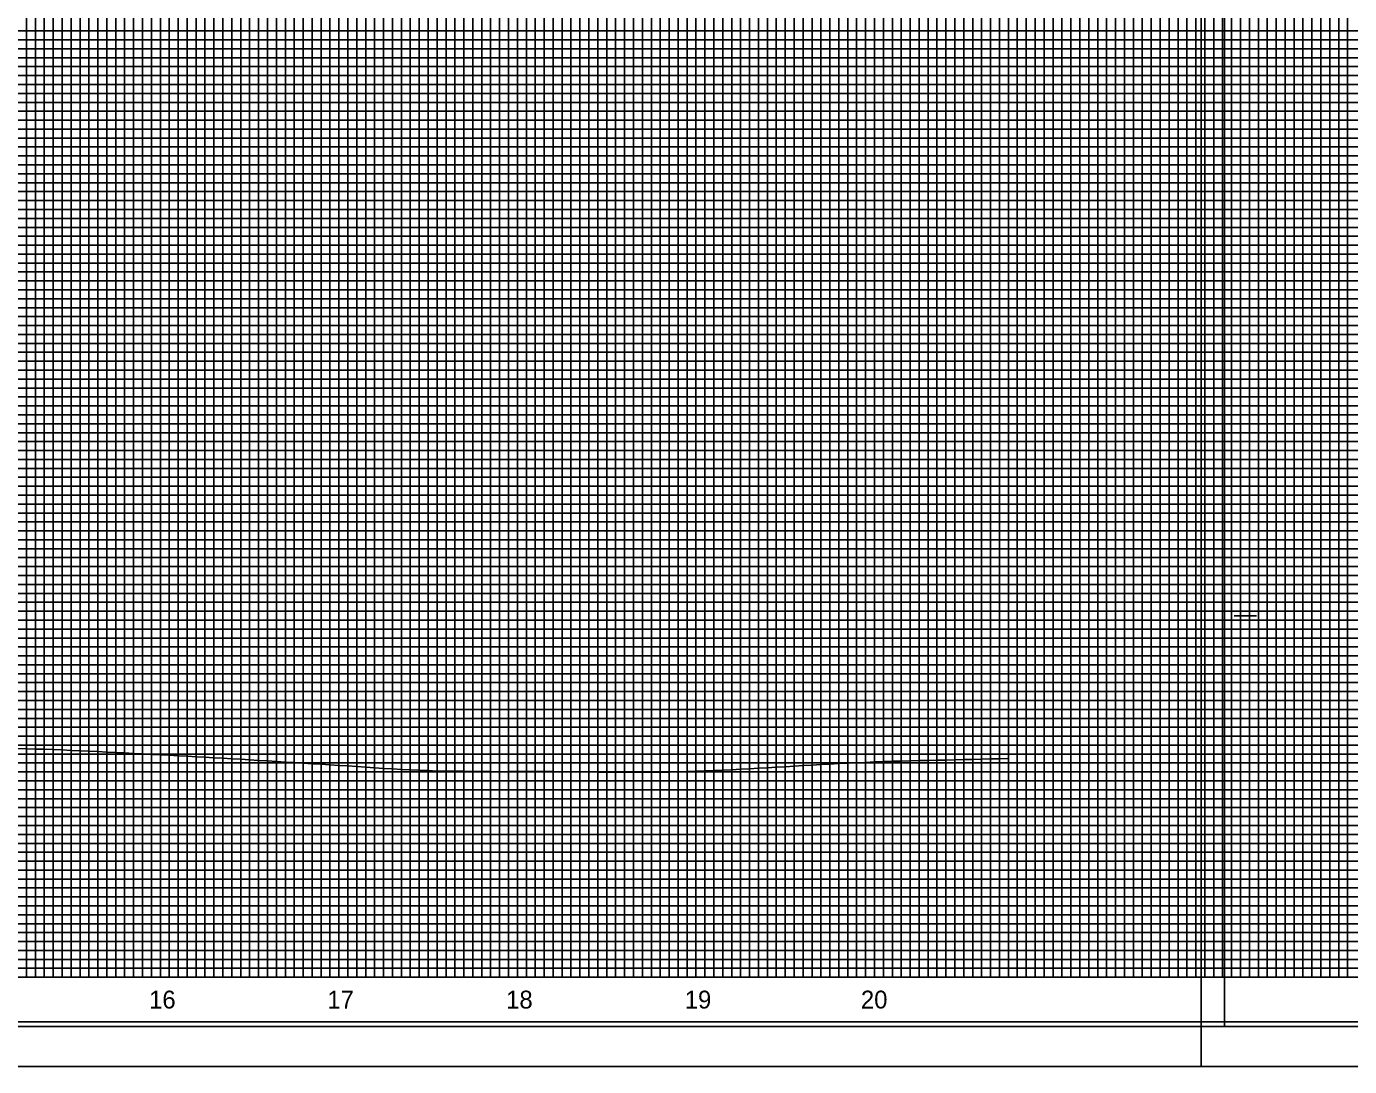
# Model space of a CAD drawing. Extents: x 2345490 to 2445302, y 465165 to 573888.
# Drawn here: x 2382292 to 2383033, y 532361 to 532944 of the extents above; entities that cross this region are included whole.
import ezdxf

# ---------------------------------------------------------------- set-up
doc = ezdxf.new("R2010")
doc.units = 0
for name, color, linetype in [('Old_Level_1', 7, 'Continuous'), ('Old_Level_18', 7, 'Continuous'), ('Old_Level_41', 7, 'Continuous'), ('Old_Level_42', 7, 'Continuous'), ('Old_Level_43', 7, 'Continuous'), ('Old_Level_50', 7, 'Continuous'), ('Old_Level_51', 7, 'Continuous'), ('Old_Level_52', 7, 'Continuous'), ('Old_Level_62', 7, 'Continuous')]:
    doc.layers.add(name, color=color, linetype=linetype)

msp = doc.modelspace()

# ---------------------------------------------------------------- linework, layer by layer
at = {"layer": 'Old_Level_1'}
for points in [[(2382286.799, 532539.1095), (2382291.799, 532538.9875), (2382296.799, 532538.85975), (2382301.799, 532538.726), (2382306.799, 532538.5865), (2382311.799, 532538.377), (2382316.799, 532538.132), (2382321.799, 532537.8975), (2382326.799, 532537.65625), (2382331.799, 532537.4085), (2382336.799, 532537.15425), (2382341.799, 532536.908), (2382346.799, 532536.6585), (2382351.799, 532536.403), (2382356.799, 532536.14075), (2382361.799, 532535.87225), (2382366.799, 532535.60075), (2382371.799, 532535.38675), (2382376.799, 532535.12375), (2382381.799, 532534.849), (2382386.799, 532534.5685), (2382391.799, 532534.282), (2382396.799, 532533.99625), (2382401.799, 532533.748), (2382406.799, 532533.447), (2382411.799, 532533.1405), (2382416.799, 532532.8285), (2382421.799, 532532.51075), (2382426.799, 532532.18825), (2382431.799, 532531.8715), (2382436.799, 532531.56825), (2382441.799, 532531.25975), (2382446.799, 532530.94575), (2382451.799, 532530.6265), (2382456.799, 532530.3015), (2382461.799, 532529.98825), (2382466.799, 532529.706), (2382471.799, 532529.38325), (2382476.799, 532529.05375), (2382481.799, 532528.71925), (2382486.799, 532528.37975), (2382491.799, 532528.03575), (2382496.799, 532527.726), (2382501.799, 532527.4785), (2382506.799, 532527.238), (2382511.799, 532526.99725), (2382516.799, 532526.7565), (2382521.799, 532526.516), (2382526.799, 532526.498), (2382531.799, 532526.46275), (2382536.799, 532526.39975), (2382541.799, 532526.3365), (2382546.799, 532526.2735), (2382551.799, 532526.21025), (2382556.799, 532526.18925), (2382561.799, 532526.358), (2382566.799, 532526.34), (2382571.799, 532526.32175), (2382576.799, 532526.30375), (2382581.799, 532526.2855), (2382586.799, 532526.26725), (2382591.799, 532526.192), (2382596.799, 532526.11125), (2382601.799, 532526.06925), (2382606.799, 532526.02725), (2382611.799, 532525.985), (2382616.799, 532525.943), (2382621.799, 532525.88875), (2382626.799, 532525.86325), (2382631.799, 532525.86525), (2382636.799, 532525.86725), (2382641.799, 532525.869), (2382646.799, 532525.871), (2382651.799, 532525.968), (2382656.799, 532526.135), (2382661.799, 532526.315), (2382666.799, 532526.49525), (2382671.799, 532526.67525), (2382676.799, 532526.8555), (2382681.799, 532527.05), (2382686.799, 532527.29475), (2382691.799, 532527.573), (2382696.799, 532527.851), (2382701.799, 532528.12925), (2382706.799, 532528.4075), (2382711.799, 532528.67275), (2382716.799, 532528.94875), (2382721.799, 532529.25225), (2382726.799, 532529.556), (2382731.799, 532529.8595), (2382736.799, 532530.163), (2382741.799, 532530.4535), (2382746.799, 532530.685), (2382751.799, 532530.9185), (2382756.799, 532531.152), (2382761.799, 532531.3855), (2382766.799, 532531.61925)], [(2382766.799, 532531.61925), (2382771.799, 532531.85275), (2382776.799, 532532.025), (2382781.799, 532532.15675), (2382786.799, 532532.2705), (2382791.799, 532532.38425), (2382796.799, 532532.49775), (2382801.799, 532532.6115), (2382806.799, 532532.726), (2382811.799, 532532.84175), (2382816.799, 532532.95525), (2382821.799, 532533.06875), (2382826.799, 532533.182), (2382831.799, 532533.2955), (2382836.799, 532533.409), (2382841.349, 532533.50025)]]:
    msp.add_lwpolyline(points, dxfattribs=at)
at = {"layer": 'Old_Level_18'}
msp.add_lwpolyline([(2383216.79875, 533436.04975), (2381716.79875, 533436.04975), (2381716.79875, 532386.04975), (2383216.79875, 532386.04975)], close=True, dxfattribs=at)
at = {"layer": 'Old_Level_41'}
for p, q in [((2382968.29875, 532613.54975), (2382980.79875, 532613.54975)), ((2383216.79875, 532411.04975), (2381716.79875, 532411.04975))]:
    msp.add_line(p, q, dxfattribs=at)
for points in [[(2382241.79875, 532411.04975), (2382291.79875, 532411.04975), (2382291.79875, 533436.04975)], [(2382266.79875, 532411.04975), (2382316.79875, 532411.04975), (2382316.79875, 533436.04975)], [(2382341.79875, 533436.04975), (2382341.79875, 532411.04975), (2382391.79875, 532411.04975), (2382391.79875, 533436.04975)], [(2382366.79875, 533436.04975), (2382366.79875, 532411.04975), (2382416.79875, 532411.04975), (2382416.79875, 533436.04975)], [(2382441.79875, 533436.04975), (2382441.79875, 532411.04975), (2382491.79875, 532411.04975), (2382491.79875, 533436.04975)], [(2382466.79875, 533436.04975), (2382466.79875, 532411.04975), (2382516.79875, 532411.04975), (2382516.79875, 533436.04975)], [(2382541.79875, 533436.04975), (2382541.79875, 532411.04975), (2382591.79875, 532411.04975), (2382591.79875, 533436.04975)], [(2382566.79875, 533436.04975), (2382566.79875, 532411.04975), (2382616.79875, 532411.04975), (2382616.79875, 533436.04975)], [(2382641.79875, 533436.04975), (2382641.79875, 532411.04975), (2382691.79875, 532411.04975), (2382691.79875, 533436.04975)], [(2382666.79875, 533436.04975), (2382666.79875, 532411.04975), (2382716.79875, 532411.04975), (2382716.79875, 533436.04975)], [(2382741.79875, 533436.04975), (2382741.79875, 532411.04975), (2382791.79875, 532411.04975), (2382791.79875, 533436.04975)], [(2382766.79875, 533436.04975), (2382766.79875, 532411.04975), (2382816.79875, 532411.04975), (2382816.79875, 533436.04975)], [(2382841.79875, 533436.04975), (2382841.79875, 532411.04975), (2382891.79875, 532411.04975), (2382891.79875, 533436.04975)], [(2382866.79875, 533436.04975), (2382866.79875, 532411.04975), (2382916.79875, 532411.04975), (2382916.79875, 533436.04975)], [(2382941.79875, 533436.04975), (2382941.79875, 532411.04975), (2382991.79875, 532411.04975), (2382991.79875, 533436.04975)], [(2382966.79875, 533436.04975), (2382966.79875, 532411.04975), (2383016.79875, 532411.04975), (2383016.79875, 533436.04975)], [(2383216.79875, 532936.04975), (2381716.79875, 532936.04975), (2381716.79875, 532886.04975), (2383216.79875, 532886.04975)], [(2383216.79875, 532836.04975), (2381716.79875, 532836.04975), (2381716.79875, 532786.04975), (2383216.79875, 532786.04975)], [(2383216.79875, 532761.04975), (2381716.79875, 532761.04975), (2381716.79875, 532811.04975), (2383216.79875, 532811.04975)], [(2383216.79875, 532736.04975), (2381716.79875, 532736.04975), (2381716.79875, 532686.04975), (2383216.79875, 532686.04975)], [(2383216.79875, 532661.04975), (2381716.79875, 532661.04975), (2381716.79875, 532711.04975), (2383216.79875, 532711.04975)], [(2383216.79875, 532636.04975), (2381716.79875, 532636.04975), (2381716.79875, 532586.04975), (2383216.79875, 532586.04975)], [(2383216.79875, 532536.04975), (2381716.79875, 532536.04975), (2381716.79875, 532486.04975), (2383216.79875, 532486.04975)], [(2383216.79875, 532461.04975), (2381716.79875, 532461.04975), (2381716.79875, 532511.04975), (2383216.79875, 532511.04975)], [(2383216.79875, 532436.04975), (2381716.79875, 532436.04975)]]:
    msp.add_lwpolyline(points, dxfattribs=at)
at = {"layer": 'Old_Level_42'}
for points in [[(2383216.79875, 532861.04975), (2381716.79875, 532861.04975), (2381716.79875, 532911.04975), (2383216.79875, 532911.04975)], [(2383216.79875, 532561.04975), (2381716.79875, 532561.04975), (2381716.79875, 532611.04975), (2383216.79875, 532611.04975)]]:
    msp.add_lwpolyline(points, dxfattribs=at)
at = {"layer": 'Old_Level_43'}
for points in [[(2382296.79875, 532411.04975), (2382296.79875, 533436.04975)], [(2382301.79875, 533436.04975), (2382301.79875, 532411.04975), (2382306.79875, 532411.04975), (2382306.79875, 533436.04975)], [(2382311.79875, 533436.04975), (2382311.79875, 532411.04975), (2382321.79875, 532411.04975), (2382321.79875, 533436.04975)], [(2382326.79875, 533436.04975), (2382326.79875, 532411.04975), (2382326.79875, 532411.04975), (2382331.79875, 532411.04975), (2382331.79875, 533436.04975)], [(2382336.79875, 533436.04975), (2382336.79875, 532411.04975), (2382346.79875, 532411.04975), (2382346.79875, 533436.04975)], [(2382351.79875, 533436.04975), (2382351.79875, 532411.04975), (2382356.79875, 532411.04975), (2382356.79875, 533436.04975)], [(2382361.79875, 533436.04975), (2382361.79875, 532411.04975), (2382371.79875, 532411.04975), (2382371.79875, 533436.04975)], [(2382376.79875, 533436.04975), (2382376.79875, 532411.04975), (2382381.79875, 532411.04975), (2382381.79875, 533436.04975)], [(2382386.79875, 533436.04975), (2382386.79875, 532411.04975), (2382396.79875, 532411.04975), (2382396.79875, 533436.04975)], [(2382401.79875, 533436.04975), (2382401.79875, 532411.04975), (2382406.79875, 532411.04975), (2382406.79875, 533436.04975)], [(2382411.79875, 533436.04975), (2382411.79875, 532411.04975), (2382421.79875, 532411.04975), (2382421.79875, 533436.04975)], [(2382426.79875, 533436.04975), (2382426.79875, 532411.04975), (2382431.79875, 532411.04975), (2382431.79875, 533436.04975)], [(2382436.79875, 533436.04975), (2382436.79875, 532411.04975), (2382446.79875, 532411.04975), (2382446.79875, 533436.04975)], [(2382451.79875, 533436.04975), (2382451.79875, 532411.04975), (2382456.79875, 532411.04975), (2382456.79875, 533436.04975)], [(2382461.79875, 533436.04975), (2382461.79875, 532411.04975), (2382471.79875, 532411.04975), (2382471.79875, 533436.04975)], [(2382476.79875, 533436.04975), (2382476.79875, 532411.04975)], [(2382476.79875, 532411.04975), (2382481.79875, 532411.04975), (2382481.79875, 533435.44975)], [(2382486.79875, 533435.44975), (2382486.79875, 532411.04975), (2382496.79875, 532411.04975), (2382496.79875, 533436.04975)], [(2382501.79875, 533436.04975), (2382501.79875, 532411.04975), (2382506.79875, 532411.04975), (2382506.79875, 533436.04975)], [(2382511.79875, 533436.04975), (2382511.79875, 532411.04975), (2382521.79875, 532411.04975), (2382521.79875, 533436.04975)], [(2382526.79875, 533436.04975), (2382526.79875, 532411.04975), (2382531.79875, 532411.04975), (2382531.79875, 533436.04975)], [(2382536.79875, 533436.04975), (2382536.79875, 532411.04975), (2382546.79875, 532411.04975), (2382546.79875, 533436.04975)], [(2382551.79875, 533436.04975), (2382551.79875, 532411.04975), (2382556.79875, 532411.04975), (2382556.79875, 533436.04975)], [(2382561.79875, 533436.04975), (2382561.79875, 532411.04975), (2382571.79875, 532411.04975), (2382571.79875, 533436.04975)], [(2382576.79875, 533436.04975), (2382576.79875, 532411.04975), (2382581.79875, 532411.04975), (2382581.79875, 533436.04975)], [(2382586.79875, 533436.04975), (2382586.79875, 532411.04975), (2382596.79875, 532411.04975), (2382596.79875, 533436.04975)], [(2382601.79875, 533436.04975), (2382601.79875, 532411.04975), (2382606.79875, 532411.04975), (2382606.79875, 533436.04975)], [(2382611.79875, 533436.04975), (2382611.79875, 532411.04975), (2382621.79875, 532411.04975), (2382621.79875, 533436.04975)], [(2382626.79875, 533436.04975), (2382626.79875, 532411.04975), (2382631.79875, 532411.04975), (2382631.79875, 533436.04975)], [(2382636.79875, 533436.04975), (2382636.79875, 532411.04975), (2382646.79875, 532411.04975), (2382646.79875, 533436.04975)], [(2382651.79875, 533436.04975), (2382651.79875, 532411.04975), (2382656.79875, 532411.04975), (2382656.79875, 533436.04975)], [(2382661.79875, 533436.04975), (2382661.79875, 532411.04975), (2382671.79875, 532411.04975), (2382671.79875, 533436.04975)], [(2382676.79875, 533436.04975), (2382676.79875, 532411.04975), (2382681.79875, 532411.04975), (2382681.79875, 533436.04975)], [(2382686.79875, 533436.04975), (2382686.79875, 532411.04975), (2382696.79875, 532411.04975), (2382696.79875, 533436.04975)], [(2382701.79875, 533436.04975), (2382701.79875, 532411.04975), (2382706.79875, 532411.04975), (2382706.79875, 533436.04975)], [(2382711.79875, 533436.04975), (2382711.79875, 532411.04975), (2382721.79875, 532411.04975), (2382721.79875, 533436.04975)], [(2382726.79875, 533436.04975), (2382726.79875, 532411.04975), (2382731.79875, 532411.04975), (2382731.79875, 533436.04975)], [(2382736.79875, 533436.04975), (2382736.79875, 532411.04975), (2382746.79875, 532411.04975), (2382746.79875, 533436.04975)], [(2382751.79875, 533436.04975), (2382751.79875, 532411.04975), (2382756.79875, 532411.04975), (2382756.79875, 533436.04975)], [(2382761.79875, 533436.04975), (2382761.79875, 532411.04975), (2382771.79875, 532411.04975), (2382771.79875, 533436.04975)], [(2382776.79875, 533436.04975), (2382776.79875, 532411.04975), (2382781.79875, 532411.04975), (2382781.79875, 533436.04975)], [(2382786.79875, 533436.04975), (2382786.79875, 532411.04975)], [(2382786.79875, 532411.04975), (2382796.79875, 532411.04975), (2382796.79875, 533436.04975)], [(2382801.79875, 533436.04975), (2382801.79875, 532411.04975), (2382806.79875, 532411.04975), (2382806.79875, 533436.04975)], [(2382811.79875, 533436.04975), (2382811.79875, 532411.04975), (2382821.79875, 532411.04975), (2382821.79875, 533436.04975)], [(2382826.79875, 533436.04975), (2382826.79875, 532411.04975), (2382831.79875, 532411.04975), (2382831.79875, 533436.04975)], [(2382836.79875, 533436.04975), (2382836.79875, 532411.04975), (2382846.79875, 532411.04975), (2382846.79875, 533436.04975)], [(2382851.79875, 533436.04975), (2382851.79875, 532411.04975), (2382856.79875, 532411.04975), (2382856.79875, 533436.04975)], [(2382861.79875, 533436.04975), (2382861.79875, 532411.04975), (2382871.79875, 532411.04975), (2382871.79875, 533436.04975)], [(2382876.79875, 533436.04975), (2382876.79875, 532411.04975), (2382881.79875, 532411.04975), (2382881.79875, 533436.04975)], [(2382886.79875, 533436.04975), (2382886.79875, 532411.04975), (2382896.79875, 532411.04975), (2382896.79875, 533436.04975)], [(2382901.79875, 533436.04975), (2382901.79875, 532411.04975), (2382906.79875, 532411.04975), (2382906.79875, 533436.04975)], [(2382911.79875, 533436.04975), (2382911.79875, 532411.04975), (2382921.79875, 532411.04975), (2382921.79875, 533436.04975)], [(2382926.79875, 533436.04975), (2382926.79875, 532411.04975), (2382931.79875, 532411.04975), (2382931.79875, 533436.04975)], [(2382936.79875, 533436.04975), (2382936.79875, 532411.04975), (2382946.79875, 532411.04975), (2382946.79875, 533436.04975)], [(2382951.79875, 533436.04975), (2382951.79875, 532411.04975), (2382956.79875, 532411.04975), (2382956.79875, 533436.04975)], [(2382961.79875, 533436.04975), (2382961.79875, 532411.04975), (2382971.79875, 532411.04975), (2382971.79875, 533436.04975)], [(2382976.79875, 533436.04975), (2382976.79875, 532411.04975), (2382981.79875, 532411.04975), (2382981.79875, 533436.04975)], [(2382986.79875, 533436.04975), (2382986.79875, 532411.04975), (2382996.79875, 532411.04975), (2382996.79875, 533436.04975)], [(2383001.79875, 533436.04975), (2383001.79875, 532411.04975), (2383006.79875, 532411.04975), (2383006.79875, 533436.04975)], [(2383011.79875, 533436.04975), (2383011.79875, 532411.04975), (2383021.79875, 532411.04975), (2383021.79875, 533298.49975)], [(2383026.79875, 533298.49975), (2383026.79875, 532411.04975), (2383031.79875, 532411.04975), (2383031.79875, 533298.49975)], [(2383166.79875, 532941.04975), (2381766.79875, 532941.04975), (2381766.79875, 532931.04975), (2383166.79875, 532931.04975)], [(2383166.79875, 532926.04975), (2381766.79875, 532926.04975), (2381766.79875, 532921.04975), (2383166.79875, 532921.04975)], [(2383166.79875, 532916.04975), (2381766.79875, 532916.04975)], [(2381766.79875, 532906.04975), (2383166.79875, 532906.04975)], [(2383166.79875, 532901.04975), (2381766.79875, 532901.04975), (2381766.79875, 532896.04975), (2383166.79875, 532896.04975)], [(2383166.79875, 532891.04975), (2381766.79875, 532891.04975), (2381766.79875, 532881.04975), (2383166.79875, 532881.04975)], [(2383166.79875, 532876.04975), (2381766.79875, 532876.04975), (2381766.79875, 532871.04975), (2383166.79875, 532871.04975)], [(2383166.79875, 532866.04975), (2381766.79875, 532866.04975), (2381766.79875, 532856.04975), (2383166.79875, 532856.04975)], [(2383166.79875, 532851.04975), (2381766.79875, 532851.04975), (2381766.79875, 532846.04975), (2383166.79875, 532846.04975)], [(2383166.79875, 532841.04975), (2381766.79875, 532841.04975), (2381766.79875, 532831.04975), (2383166.79875, 532831.04975)], [(2383166.79875, 532826.04975), (2381766.79875, 532826.04975), (2381766.79875, 532821.04975), (2383166.79875, 532821.04975)], [(2383166.79875, 532816.04975), (2381766.79875, 532816.04975), (2381766.79875, 532806.04975), (2383166.79875, 532806.04975)], [(2383166.79875, 532801.04975), (2381766.79875, 532801.04975), (2381766.79875, 532796.04975), (2383166.79875, 532796.04975)], [(2383166.79875, 532791.04975), (2381766.79875, 532791.04975), (2381766.79875, 532781.04975), (2383166.79875, 532781.04975)], [(2383166.79875, 532776.04975), (2381766.79875, 532776.04975), (2381766.79875, 532771.04975), (2383166.79875, 532771.04975)], [(2383166.79875, 532766.04975), (2381766.79875, 532766.04975), (2381766.79875, 532756.04975), (2383166.79875, 532756.04975)], [(2383166.79875, 532751.04975), (2381766.79875, 532751.04975), (2381766.79875, 532746.04975), (2383166.79875, 532746.04975)], [(2383166.79875, 532741.04975), (2381766.79875, 532741.04975), (2381766.79875, 532731.04975), (2383166.79875, 532731.04975)], [(2383166.79875, 532726.04975), (2381766.79875, 532726.04975), (2381766.79875, 532721.04975), (2383166.79875, 532721.04975)], [(2383166.79875, 532716.04975), (2381766.79875, 532716.04975), (2381766.79875, 532706.04975), (2383166.79875, 532706.04975)], [(2383166.79875, 532701.04975), (2381766.79875, 532701.04975), (2381766.79875, 532696.04975), (2383166.79875, 532696.04975)], [(2383166.79875, 532691.04975), (2381766.79875, 532691.04975), (2381766.79875, 532681.04975), (2383166.79875, 532681.04975)], [(2383166.79875, 532676.04975), (2381766.79875, 532676.04975), (2381766.79875, 532671.04975), (2383166.79875, 532671.04975)], [(2383166.79875, 532666.04975), (2381766.79875, 532666.04975), (2381766.79875, 532656.04975), (2383166.79875, 532656.04975)], [(2383166.79875, 532651.04975), (2381766.79875, 532651.04975), (2381766.79875, 532646.04975), (2383166.79875, 532646.04975)], [(2383166.79875, 532641.04975), (2381766.79875, 532641.04975), (2381766.79875, 532631.04975), (2383166.79875, 532631.04975)], [(2383166.79875, 532626.04975), (2381766.79875, 532626.04975), (2381766.79875, 532621.04975), (2383166.79875, 532621.04975)], [(2383166.79875, 532616.04975), (2381766.79875, 532616.04975)], [(2381766.79875, 532606.04975), (2383166.79875, 532606.04975)], [(2383166.79875, 532601.04975), (2381766.79875, 532601.04975), (2381766.79875, 532596.04975), (2383166.79875, 532596.04975)], [(2383166.79875, 532591.04975), (2381766.79875, 532591.04975)], [(2381766.79875, 532581.04975), (2383166.79875, 532581.04975)], [(2383166.79875, 532576.04975), (2381766.79875, 532576.04975), (2381766.79875, 532571.04975), (2383166.79875, 532571.04975)], [(2383166.79875, 532566.04975), (2381766.79875, 532566.04975), (2381766.79875, 532556.04975), (2383166.79875, 532556.04975)], [(2383166.79875, 532551.04975), (2381766.79875, 532551.04975), (2381766.79875, 532546.04975), (2383166.79875, 532546.04975)], [(2383166.79875, 532541.04975), (2381766.79875, 532541.04975), (2381766.79875, 532531.04975), (2383166.79875, 532531.04975)], [(2383166.79875, 532526.04975), (2381766.79875, 532526.04975), (2381766.79875, 532521.04975), (2383166.79875, 532521.04975)], [(2383166.79875, 532516.04975), (2381766.79875, 532516.04975), (2381766.79875, 532506.04975), (2383166.79875, 532506.04975)], [(2383166.79875, 532501.04975), (2381766.79875, 532501.04975), (2381766.79875, 532496.04975), (2383166.79875, 532496.04975)], [(2383166.79875, 532491.04975), (2381766.79875, 532491.04975), (2381766.79875, 532481.04975), (2383166.79875, 532481.04975)], [(2383166.79875, 532476.04975), (2381766.79875, 532476.04975), (2381766.79875, 532471.04975), (2383166.79875, 532471.04975)], [(2383166.79875, 532466.04975), (2381766.79875, 532466.04975), (2381766.79875, 532456.04975), (2383166.79875, 532456.04975)], [(2383166.79875, 532451.04975), (2381766.79875, 532451.04975), (2381766.79875, 532446.04975), (2383166.79875, 532446.04975)], [(2383166.79875, 532441.04975), (2381766.79875, 532441.04975), (2381766.79875, 532431.04975), (2383166.79875, 532431.04975)], [(2383166.79875, 532426.04975), (2381766.79875, 532426.04975), (2381766.79875, 532421.04975), (2383166.79875, 532421.04975)], [(2383166.79875, 532416.04975), (2381766.79875, 532416.04975)]]:
    msp.add_lwpolyline(points, dxfattribs=at)
at = {"layer": 'Old_Level_50'}
msp.add_line((2382949.79875, 532361.04975), (2382949.79875, 532361.04975), dxfattribs=at)
for points in [[(2383229.29875, 533438.59975), (2381562.79875, 533438.59975), (2381562.79875, 532383.49975), (2383229.29875, 532383.49975)], [(2384629.29875, 533438.59975), (2382962.79875, 533438.59975), (2382962.79875, 532383.49975), (2384629.29875, 532383.49975)]]:
    msp.add_lwpolyline(points, close=True, dxfattribs=at)
at = {"layer": 'Old_Level_51'}
for points in [[(2383233.79875, 533461.04975), (2381549.79875, 533461.04975), (2381549.79875, 532361.04975), (2383233.79875, 532361.04975)], [(2384633.79875, 533461.04975), (2382949.79875, 533461.04975), (2382949.79875, 532361.04975), (2384633.79875, 532361.04975)]]:
    msp.add_lwpolyline(points, close=True, dxfattribs=at)
at = {"layer": 'Old_Level_52'}
msp.add_line((2382962.79875, 532383.49975), (2382962.79875, 532383.49975), dxfattribs=at)

# ---------------------------------------------------------------- texts
at = {"layer": 'Old_Level_62'}
for s, p in [('16', (2382360.481, 532393.55)), ('17', (2382460.3385, 532393.55)), ('18', (2382560.46425, 532393.55)), ('19', (2382660.5065, 532393.55)), ('20', (2382759.1855, 532393.55))]:
    msp.add_text(s, height=10.000001, dxfattribs=at).set_placement(p)

doc.saveas('drawing.dxf')
